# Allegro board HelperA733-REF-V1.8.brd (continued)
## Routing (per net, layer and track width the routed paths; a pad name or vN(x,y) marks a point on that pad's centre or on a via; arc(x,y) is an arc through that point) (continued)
GND_485: length 32.8
  TOP w0.254: C60.2 116.63,18.03 116.63,18.05
  TOP w0.381: R75.1 114.39,14.01 v1(113.81,14.01) 113.24,14.01 R76.1 ; D54.1 106.96,15.44 107.79,16.26 110.01,16.26 110.01,15.63
  TOP w0.508: C59.2 115.31,18.41 115.31,23.55 114.74,24.13 R72.2 ; C59.2 114.78,17.88 110.72,17.88 110.01,17.16 110.01,16.26 ; C59.2 115.31,18.45 116.18,18.45 C60.2
  BOTTOM w0.381: v1(113.81,14.01) 110.39,14.01 110.39,14.01 v1(106.97,14.01)
VBUS1: length 52.5
  TOP w0.152: D64.2 25.83,87 25.92,86.91 26.01,87 CU2.2 ; 25.92,85.57 25.94,85.6 CU3.2 ; 25.89,84.48 26.51,84.48 26.61,84.38 U13.1
  TOP w1.524: J22.4 9.64,87 10.58,87.94 10.58,98.6 12.07,100.09 23.99,100.09 25.11,98.97 J20.5 J20.1 25.11,89.19 25.92,88.38 25.92,85.57 25.89,85.54 25.89,84.48
  BOTTOM w1.524: J23.4 J22.4
VBUS-EN: length 84.1
  TOP w0.152: U1.172 60.11,33.7 62.71,36.3 v1(62.71,66.7) ; v1(32.03,82.16) 31.92,82.01 30.81,80.9 RU1.2 29.54,82.03 U13.4
  BOTTOM w0.152: v1(32.03,82.16) 40.03,82.16 40.49,81.7 40.49,68.88 42.37,67 62.41,67 v1(62.71,66.7)
VBUS-USB: length 21.6
  TOP w0.3: J19.B4 81.91,99.6 82.41,100.1 86.21,100.1 86.71,99.6 J19.A4
  TOP w0.305: 80.51,89.68 79.69,89.68
  TOP w0.635: J19.B4 81.91,97.16 D63.1 ; 78.24,91 78.41,90.83 ; 78.41,90.83 78.82,90.42 C66.1 ; 78.41,90.83 78.41,95.45 79.07,96.11
  TOP w0.762: 79.69,89.68 78.82,89.68 C66.1 ; C63.2 79.07,96.11 79.32,96.36 D63.1
VCC-1V8: length 243.7
  TOP w0.152: v1(48.81,62.2) 48.81,63.1 48.76,63.15 Q9.1 ; C20.2 76.01,96.73 76.12,96.84 U5.2 ; v1(103.51,13.83) 104.11,13.23 104.11,11.86 105.66,10.31 105.66,8.31 109.63,4.34 115.94,4.34 123.11,11.51 135.69,11.51 R54.1 ; 44.01,58.88 43.51,59.38 43.51,59.9 42.51,60.9 v1(42.51,62.2) 42.46,62.25 Q11.1 ; v1(64.91,17) 64.91,26.25 72.31,33.65 v1(72.31,62.7) 72.31,71.27 v1(72.3,71.27) ; 46.51,58.88 45.91,59.48 45.91,61.9 v1(45.61,62.2) 45.61,63.24 Q10.1 ; 41.51,58.88 40.01,60.38 v1(40.01,62.2) ; v1(68.11,11.7) R50.1 ; R48.1 R49.1 69.41,11.5 69.51,11.6 v1(69.51,11.7) ; 73.69,90.8 75.01,90.8 75.21,90.6 75.21,89.7 76.51,88.4 76.51,84.8 v1(78.51,82.8)
  TOP w0.5: 76.12,97.9 U5.2 ; RA20.1 73.69,90.97 76.66,93.95 76.66,95.87 76.51,96.03 C20.2
  BOTTOM w0.152: v1(40.01,62.2) v1(42.51,62.2) v1(45.61,62.2) v1(48.81,62.2) 51.21,62.2 51.71,62.7 72.21,62.7 72.26,62.65 v1(72.31,62.7) ; v1(103.51,13.83) 102.2,13.83 101.37,14.67 97.93,14.67 94.93,17.66 65.57,17.66 v1(64.91,17) 64.91,14.9 v1(68.11,11.7) v1(69.51,11.7) ; v1(72.3,71.27) 72.31,74 72.31,79.5 72.91,80.1 76,80.1 76.45,79.66 77.95,79.66 78.19,79.42 78.63,79.42 78.93,79.71 78.93,82.38 v1(78.51,82.8)
VCC-3V3: length 506.2
  TOP w0.152: v1(110.76,23.26) 110.27,23.26 109.11,22.1 R69.2 ; 144.31,71.9 v1(144.51,72.2) ; D56.2 43.79,19.82 44.11,19.5 45.71,19.5 46.14,19.08 R80.1 R79.1 R77.1 R78.1 ; v1(137.41,57.1) R27.1 ; v1(140.01,72) 139.61,72 139.51,71.9 R17.1 R31.1 ; Q3.1 130.31,23.65 v1(130.31,22.7) 131.64,22.7 R87.2 ; R25.2 136.95,43.45 v1(136.26,43.45) ; 38.51,16.9 38.41,16.9 38.54,17.03 ; 38.51,16.9 38.51,16.64 R119.1 ; 38.51,16.9 38.53,16.9 ; 127.01,19.9 126.96,19.85 v1(126.91,19.9) ; J4.3 141.71,71.9 140.51,73.1 v1(140.41,73.1) ; v1(107.41,84.4) 107.41,85.1 108.56,86.25 R51.1 ; R28.1 v1(138.21,53)
  TOP w0.254: C84.1 23.98,80.46 23.25,80.46 23.16,80.38 ; v1(63.51,81.5) 63.36,81.5 61.35,83.51 61.35,91.04 61.99,91.68 RA16.1 ; U42.9 18.47,80.34 18.94,79.87 21.43,79.87 21.44,79.86 21.9,79.86 21.91,79.87 22.65,79.87 23.16,80.38 ; 23.16,80.38 23.14,80.38 C87.1 ; R52.1 99.51,87.5 99.51,86.91 v1(99.57,86.91) ; v1(67.33,80.98) 67.81,81.46 RA24.1 ; R24.2 v1(136.31,44.93) ; v1(76.52,80.76) 75.7,81.58 RA22.2 ; v1(71.23,80.98) 71.23,81.58 RA23.2 71.21,81.58 ; 108.64,87.5 R51.1 ; R23.2 136.58,42.03 136.46,41.91 v1(136.46,41.44)
  TOP w0.3: v1(77.91,96.4) 77.71,96.4 77.71,93.32 76.45,92.07 76.45,89.11 76.91,88.65 76.91,85.2 78.73,83.38 78.75,83.38 79.09,83.04 79.09,81.4 v1(78.33,80.63) ; v1(61.74,81.63) 61.59,81.48 55.34,81.48 51.83,85 44.44,85 43.03,83.59 39.06,83.59 38.37,82.9 33.81,82.9 30.91,80 25.7,80 C84.1 ; v1(63.51,81.5) 63.51,81.31 64.43,80.39 66.74,80.39 v1(67.33,80.98) ; R24.2 136.95,45.4 137.15,45.6 139.71,45.6 140.01,45.3 J5.2 ; J4.2 144.01,72.4 144.31,72.1 144.31,71.9 J4.3
  TOP w0.305: v1(114.63,23.27) 114.63,19.26 113.91,18.55 110.41,18.55 109.38,17.51 Q1.2 ; 148.21,45.3 J5.2 ; 142.71,72.4 J4.2
  TOP w0.5: J15.1 34.43,10.91 37.22,13.71 38.72,13.71 39.3,14.29 39.3,15.66 38.53,16.43 R119.1 ; FB2.1 107.41,82.05 v1(107.41,84.4) ; v1(101.61,96.3) 101.66,96.25 J7.4
  TOP w0.508: v1(110.76,23.26) 110.76,23.28 C61.1
  TOP w0.6: D56.2 43.49,20.9 J17.1
  TOP w0.762: C45.2 102.94,88.38 D36.2 101.66,88.38 J7.4
  TOP w1: R119.1 38.53,19.18 38.41,19.3 J17.1 ; v1(148.21,49.5) v1(148.21,48.7) 148.21,22.29 144.42,18.5 139.95,18.5 134.35,12.9 127.59,12.9 126.91,13.58 v1(126.91,19.9) ; 127.01,19.9 v1(127.61,19.9) D70.1
  BOTTOM w0.152: v1(140.01,72) 140.01,72.6 140.46,73.05 v1(140.41,73.1) ; v1(130.31,22.7) 130.31,20.2 130.01,19.9 v1(127.61,19.9)
  BOTTOM w0.254: v1(101.61,89.2) 99.87,89.2 99.57,88.9 v1(99.57,86.91) ; 78.33,80.61 v1(78.33,80.63) ; v1(136.46,41.44) 136.31,41.59 v1(136.31,44.93) 136.31,46.8 138.21,48.7 v1(138.21,53) 138.21,56.6 137.71,57.1 v1(137.41,57.1)
  BOTTOM w0.3: 76.5,80.74 76.45,80.8 71.41,80.8 v1(71.23,80.98) 70.91,81.3 67.65,81.3 v1(67.33,80.98) ; 76.5,80.74 v1(76.52,80.76) ; 76.5,80.74 76.91,80.34 78.01,80.34 78.31,80.64 v1(78.33,80.63) ; v1(61.74,81.63) 61.74,81.6 63.41,81.6 v1(63.51,81.5)
  BOTTOM w0.5: J16.3 60.61,7.74 59.8,8.55 42.26,8.55 39.9,10.91 J14.1 J15.1 ; v1(101.61,96.3) 101.51,96.4 89.81,96.4 88.21,98 78.91,98 77.91,97 v1(77.91,96.4)
  BOTTOM w0.508: v1(114.63,23.27) 116.15,23.27 116.15,23.27 116.1,23.18
  BOTTOM w1: v1(114.63,23.27) 114.63,23.26 ; 114.63,23.26 v1(110.76,23.26) 105.2,23.26 105.17,23.3 89.81,23.3 87.01,20.5 57.01,20.5 56.31,21.2 51.64,21.2 51.01,20.58 38.74,20.58 J17.1 ; 114.63,23.26 120.35,23.26 123.71,19.9 v1(126.91,19.9) v1(127.61,19.9) ; v1(101.61,89.2) 106.41,84.4 v1(107.41,84.4) 132.31,84.4 v1(144.51,72.2) 146.61,70.1 146.61,52.9 148.21,51.3 v1(148.21,49.5) v1(148.21,48.7)
VCC_4G: length 73.5
  TOP w0.152: R117.1 C92.1 ; CON3.2 28.74,66.28 28.81,66.2 ; C99.1 C101.1 28.29,53.69 C94.1 25.5,51.71 25.39,51.6 L7.2 ; D73.1 7.71,79 9.11,77.6 CON3.41
  TOP w0.3: R100.2 17.99,62.92 15.91,64.99 CON3.24
  TOP w0.6: 15.91,67.86 CON3.24 ; 4.71,68.4 CON3.52
  TOP w0.635: 4.71,68.4 4.71,69 4.91,69.2 ; CON3.39 9.91,73.7 9.28,73.7 9.11,73.87 CON3.41
  TOP w1: 15.91,69.2 15.91,67.86
  TOP w1.524: 4.71,68.4 5.51,69.2 9.41,69.2 ; C100.1 28.29,59.98 28.81,60.5 28.81,67.9 27.51,69.2 9.41,69.2 ; 9.41,69.2 9.41,73.56 9.28,73.7
VPP/VCC: length 5
  TOP w0.203: UA1.15 65.6,87.08 65.52,87.08
  TOP w0.254: 65.52,87.08 65.51,87.08 64.9,87.69 64.22,87.69 63.84,87.3 63.73,87.26 63.73,85.39 63.84,85.4
VRN/AGND: length 2.9
  TOP w0.203: UA1.6 68.69,90.17
  TOP w0.254: RA26.1 67.41,91.56 67.58,91.56 68.68,90.46 68.68,90.18 68.69,90.17 68.69,90.17
VRP/AVCC: length 2.7
  TOP w0.203: UA1.5 69.09,90.25
  TOP w0.254: 69.09,90.25 69.09,90.63 68.44,91.27 68.44,91.52 CA1.2
4G-EN: length 71.4
  TOP w0.152: U1.173 59.71,32.7 63.11,36.1 63.11,46 v1(63.31,46.2) ; R118.1 v1(19.71,57.6) 20.77,57.6 20.82,57.55 U43.4
  BOTTOM w0.152: v1(19.71,57.6) 19.71,50.02 20.14,49.6 38.61,49.6 42.81,45.4 60.91,45.4 61.71,46.2 v1(63.31,46.2)
340_3V3: length 16.3
  TOP w0.203: U11.9 85.14,89.15
  TOP w0.381: U12.7 83.31,86 82.91,86.4 82.91,87.2 83.21,87.5 U12.10 84.99,87.5
  TOP w0.508: C68.1 87.29,89.81 87.29,89.1 ; 87.29,87.5 87.29,85.19 C71.1 86.6,84.44 86.54,84.44 ; 87.29,87.5 87.29,89.1 ; 87.29,87.5 84.99,87.5 ; 87.29,89.1 87.24,89.15 85.14,89.15
485_1+: length 14
  TOP w0.381: R73.2 R70.2 ; R73.2 110.41,14 110.31,14.06 111.28,15.02 U9.6 ; R73.2 110.39,13.23 D53.1 110.35,12.3 110.94,11.72 110.94,10.67 D54.2 110.92,9.74 110.92,6.95 J13.2
485_1-: length 13.4
  TOP w0.381: R76.2 112.39,12.88 D53.2 112.01,12.3 111.47,11.76 111.47,10.69 D52.1 111.41,9.65 111.41,6.5 J13.1 ; R76.2 R73.1 ; R76.2 112.39,15.63 U9.7
AECRN: length 1.5
  TOP w0.152: 65.34,95.1 65.34,95.3 66.39,95.3 RA25.1
AECRP: length 1.4
  TOP w0.152: RA21.1 66.39,95.9 65.34,95.9 65.34,96.1
AFVCC-CSI: length 14.4
  TOP w0.305: 89.52,7.23 89.36,7.08 CON1.36
  TOP w0.381: 90.29,8.01 89.52,7.23
  TOP w0.508: 90.29,8.01 93.17,8.01 93.81,8.64 93.81,10.47 93.62,10.66 D9.2 CP1.1 93.64,12.08 93.81,12.25 93.81,14.4 94.01,14.6 94.01,14.97 U1.34
AGND/VRP: length 3.3
  TOP w0.203: UA1.7 68.29,90.27 68.22,90.34
  TOP w0.254: 68.22,90.34 67.44,91.13 66.96,91.13 RA4.1
AP-RESET: length 114.5
  TOP w0.152: v1(53.81,18.3) 53.51,18.6 53.51,19 55.51,21 55.51,23.6 56.01,24.1 56.01,35.9 58.81,38.7 U1.167 ; K3.2 130.31,9.24 D40.2 130.57,10.13 130.1,10.6 123.38,10.6 116.18,3.4 108.97,3.4 104.71,7.66 104.71,9.84 102.46,12.09 102.46,14.31 v1(102.14,14.63)
  BOTTOM w0.152: v1(53.81,18.3) 55.06,18.3 55.22,18.14 94.82,18.14 97.98,14.98 101.79,14.98 v1(102.14,14.63)
AVCC/VRA1: length 4.8
  TOP w0.203: UA1.8 67.89,90.07 67.78,90.18
  TOP w0.254: 67.78,90.18 67.24,90.72 66.79,90.72 66.42,91.1 65.92,91.1 65.41,91.6 65.41,91.63 64.46,91.63 RA15.2
BL-PWMI: length 4.3
  TOP w0.152: CL1.1 R26.1 11.54,43.99 11.54,44 11.58,43.96 ; CL1.1 RL1.2 ; CL1.1 RL2.2
CLKOUT-125M: length 2.5
  TOP w0.203: RE12.2 119.59,75.1 U10.35
CLKREQN: length 10.7
  TOP w0.152: J12.52 48.01,66.4 47.51,65.9 45.31,65.9 44.61,65.2 Q10.3 44.61,60.33 R230.2
CODEC-AVCC: length 43.9
  TOP w0.152: 73.63,82.2 RA13.1
  TOP w0.203: UA1.25 68.69,83.36 ; 71.99,85.88 UA1.33
  TOP w0.254: RA15.1 RA16.2 62.37,92.53 v1(62.37,92.51) 62.21,92.53 61.81,92.53 60.94,91.65 60.94,83.24 64.17,80.01 68.11,80.01 68.69,80.59 68.69,82.76 v1(68.5,82.96) 68.5,82.96 68.69,83.15 68.69,83.36 ; 73.79,84.2 CA16.2 ; CA16.2 73.64,84.2 ; CA16.2 RA17.2 73.29,82.8 v1(73.29,82.7) 73.29,82.54 73.63,82.2 ; 73.64,84.2 73.67,84.17 ; 73.64,84.2 73.01,84.2 72.85,84.37 72.85,85.3 72.27,85.88 71.99,85.88 ; RA8.2 62.01,86.3 61.76,86.55 61.76,90.46 v1(62.38,91.08)
  BOTTOM w0.254: v1(73.29,82.7) 68.75,82.7 v1(68.5,82.96) ; v1(62.38,91.08) 62.38,92.51 v1(62.37,92.51)
CODEC-CPVDD: length 31.8
  TOP w0.254: RA7.1 62.25,85.4 61.88,85.02 61.88,83.56 63.34,82.1 63.71,82.1 64.24,81.58 64.67,81.58 ; 64.67,81.58 RA14.1 ; 64.67,81.58 v1(64.67,80.98) ; 74.54,89.29 74.56,89.25 RA18.1 75.12,89.2 76.11,88.21 76.11,84.62 77.91,82.82 77.91,82.48 78.32,82.07 v1(78.32,81.76)
  TOP w0.3: RA20.2 RA18.1
  BOTTOM w0.254: v1(78.32,81.76) 76.32,81.76 76.16,81.6 72.85,81.6 72.45,82 65.53,82 64.97,81.44 64.97,81.28 v1(64.67,80.98)
CODEC-IRQ: length 23.1
  TOP w0.152: v1(78.42,79.92) 78.63,79.71 81.24,79.71 83.38,77.57 83.38,76.33 U1.108 ; UA1.24 68.29,83.47 67.81,82.99 RA24.2 68.33,81.9 68.33,81.03 v1(68.01,80.71)
  BOTTOM w0.152: v1(68.01,80.71) 68.22,80.92 70.57,80.92 71.08,80.41 76.15,80.41 76.63,79.92 v1(78.42,79.92)
CODEC-RST: length 11.8
  TOP w0.152: U1.109 83.01,77.51 81.11,79.41 78.21,79.41 77.79,79.83 77.79,82.05 RA19.2
CPVDD: length 4.3
  TOP w0.203: UA1.22 67.49,83.82 67.35,83.68
  TOP w0.254: RA14.2 CA13.1 65.71,83.22 66.1,83.62 67.28,83.62 67.35,83.68 67.35,83.68
CTP0-INT: length 109.6
  TOP w0.152: U1.180 59.21,25.7 59.31,25.76 59.34,25.7 59.61,25.7 65.81,31.9 v1(65.81,33.9) ; J5.4 142.61,44.23 142.06,44.23 v1(141.61,44.2) ; v1(141.66,42.05) 141.66,42.03 D20.6 D20.5 R23.1 137.33,42.51 136.17,42.51 135.65,41.99 135.65,39.05 132.15,35.55 128.19,35.55 127.26,36.49 127.26,39.45 128.01,40.2 129.71,40.2 J3.3
  BOTTOM w0.152: J3.3 129.71,40.2 125.87,40.2 122.47,36.8 97.11,36.8 93.91,33.6 67.01,33.6 66.71,33.9 v1(65.81,33.9) ; v1(141.61,44.2) 141.61,43.15 141.66,43.1 v1(141.66,42.05)
CTP0-RST: length 104.2
  TOP w0.152: v1(140.91,46.1) 140.81,46.1 141.11,45.8 J5.1 ; v1(140.91,42.55) 140.99,42.54 140.99,42.53 D20.7 D20.4 138.15,42.53 137.88,42.8 135.86,42.8 135.4,42.34 135.4,39.16 132.09,35.85 128.25,35.85 127.51,36.59 127.51,38.55 128.16,39.2 J3.4 ; U1.181 59.21,24.7 66.51,32 v1(66.51,33.2)
  BOTTOM w0.152: J3.4 125.44,39.2 122.74,36.49 98.41,36.49 98.4,36.5 97.21,36.5 94.01,33.3 66.71,33.3 66.61,33.2 v1(66.51,33.2) ; v1(140.91,42.55) 140.92,42.56 140.92,45.79 v1(140.91,46.1)
DC_EN: length 1.6
  TOP w0.152: U2.4 13.72,22.09 13.71,22.1 R5.2
DCIN: length 59.3
  TOP w0.152: 18.4,43.23 C10.1 ; R240.2 23.01,17.4 22.91,17.3 20.14,17.3 19.91,17.53 19.91,18.7 C3.1 ; 11.41,21.38 12.07,22.1 R5.1 ; C9.1 18.41,45.26 17.99,45.68 17.99,47.4
  TOP w0.254: 5.33,44.65 5.33,44.03 5.71,43.65 CON2.26 ; 5.33,44.65 5.07,44.39 ; 5.33,44.65 5.51,44.65 ; 5.51,44.65 6.01,45.15 CON2.29 ; 5.51,44.65 CON2.28 ; 5.51,44.65 5.51,44.4 ; CON2.27 5.71,44.15 5.47,44.39
  TOP w0.3: 17.99,47.4 R233.1
  TOP w1.524: 5.51,44.4 5.51,44.39 5.07,44.39 2.65,41.97 2.65,27.32 3.7,26.26 6.53,26.26 12.69,20.1 C2.1
DM1: length 21.3
  TOP w0.254: U42.3 13.7,83 13.57,82.87 10.65,82.87 9.71,81.93 4.01,81.93 3.34,82.6 3.34,83.59 D78.1 1.52,86.03 1.52,89.42 1.85,89.74 2.27,89.74 J23.3
DM2: length 17.2
  TOP w0.254: U42.1 13.47,84.06 13.37,83.95 10.73,83.95 9.42,82.64 7.43,82.64 7.19,82.88 7.19,83.64 D76.1 7.19,84.17 7.19,86.06 6.22,87.03 6.22,89.61 6.46,89.84 7.17,89.84 J22.3
DM3: length 10.1
  TOP w0.254: U42.15 18.31,83.53 18.54,83.61 21.56,86.63 21.56,86.66 21.9,87 D65.1 21.71,87.24 21.71,90.06 22.61,90.96 J20.2
DM4: length 23.4
  TOP w0.254: U42.13 17.51,82.47 17.28,82.55 16.64,82.55 15.85,83.35 15.85,84.65 16.63,85.43 17.1,85.43 17.33,85.67 17.33,86.64 D67.1 17.02,87 17.41,87.39 17.41,88.2 16.4,89.21 16.4,94.91 17.27,95.79 21.03,95.79 21.67,95.15 21.67,94.64 22.61,93.7
DP1: length 22.6
  TOP w0.254: J23.2 2.11,90.1 1.7,90.1 1.17,89.56 1.17,85.87 2.94,84.1 2.94,83.9 D79.1 2.67,83.82 2.64,83.82 2.98,83.48 2.98,82.45 3.86,81.57 9.86,81.57 10.8,82.51 13.58,82.51 13.63,82.47 U42.4
DP2: length 18.3
  TOP w0.254: J22.2 7.21,90.2 6.31,90.2 5.86,89.75 5.86,86.89 6.83,85.92 6.83,84.17 D77.1 6.57,83.85 6.83,83.58 6.83,82.73 7.28,82.29 9.56,82.29 10.88,83.6 13.41,83.6 13.48,83.53 U42.2
DP3: length 8.8
  TOP w0.254: J20.3 21.36,90.05 21.36,87.39 D66.1 20.97,86.95 20.96,86.95 20.96,86.54 18.48,84.06 U42.16
DP4: length 21.4
  TOP w0.254: J20.7 21.31,94.42 21.31,95 20.88,95.43 17.42,95.43 16.76,94.77 16.76,89.35 17.78,88.33 17.78,87.23 18,87 D68.1 17.69,86.64 17.69,85.52 17.24,85.07 16.78,85.07 16.2,84.5 16.2,83.49 16.79,82.91 17.37,82.91 17.45,83 U42.14
EDP-AUXN: length 63.5
  TOP w0.152: U1.135 58.54,70.23 57.71,70.23 55.88,68.4 55.88,62.35 29.51,35.98 13.99,35.98 C28.1
EDP-AUXP: length 63.4
  TOP w0.152: C25.1 13.99,35.73 29.62,35.73 56.14,62.25 56.14,68.29 57.82,69.97 58.54,69.97 58.81,69.7 U1.136
EDP-EN: length 96.5
  TOP w0.152: v1(51.58,60.51) 51.58,60.13 29.94,38.49 17.42,38.49 14.41,41.5 13.29,41.5 13.12,41.34 13.12,41.32 12.8,41 D17.2 12.56,41 12.56,41.32 11.88,42 R22.1 ; v1(63.31,61.7) 63.31,61.6 63.21,61.5 63.21,47.11 63.82,46.5 63.82,45.81 63.51,45.5 63.51,35.5 59.71,31.7 U1.174
  BOTTOM w0.152: v1(51.58,60.51) 52.87,61.8 63.31,61.8 v1(63.31,61.7)
EDP-HPD: length 66.5
  TOP w0.152: D15.2 11.57,40.56 11.54,40.53 R21.1 R20.2 13.21,39.68 13.21,39.43 R19.1 13.64,38.58 14.21,38 30.06,38 54.67,62.61 54.67,66.25 55.48,67.06 55.48,68.37 58.81,71.7 U1.134
EDP-PWM: length 96.1
  TOP w0.152: v1(64.11,61.8) 64.11,61.3 63.61,60.8 63.61,47.4 64.21,46.8 64.21,45.7 63.81,45.3 63.81,35 59.71,30.9 59.71,30.82 59.59,30.7 U1.175 ; RL1.1 14.38,42 17.48,38.9 29.78,38.9 50.81,59.93 50.81,60.33 v1(50.82,60.33)
  BOTTOM w0.152: v1(50.82,60.33) 50.82,60.56 52.56,62.3 63.61,62.3 v1(64.11,61.8)
EDP-TX0N: length 63.4
  TOP w0.152: U1.138 58.81,67.7 58.44,68.07 57.16,68.07 56.84,67.75 56.84,61.85 28.72,33.73 14.07,33.73 13.66,33.32 13.62,33.32 C23.1
EDP-TX0P: length 63.4
  TOP w0.152: C24.1 13.62,34.4 13.66,34.4 14.07,33.98 28.61,33.98 56.58,61.95 56.58,67.85 57.06,68.33 58.44,68.33 58.81,68.7 U1.137
EDP-TX1N: length 62.5
  TOP w0.152: U1.140 58.81,65.7 58.44,66.07 57.76,66.07 57.54,65.85 57.54,61.55 27.72,31.73 14.07,31.73 13.66,31.32 13.62,31.32 C21.1
EDP-TX1P: length 62.5
  TOP w0.152: C22.1 13.62,32.4 13.66,32.4 14.07,31.98 27.61,31.98 57.28,61.65 57.28,65.95 57.66,66.33 58.44,66.33 58.81,66.7 U1.139
FEL: length 121.9
  TOP w0.152: v1(62.11,38.8) 62.11,60.3 61.71,60.7 U1.145 ; v1(94.91,38.8) 95.08,38.63 95.08,20.21 95.78,19.5 97.22,19.5 98.25,18.47 98.25,17.45 102.03,13.66 102.03,11.98 104.39,9.63 104.39,7.62 108.86,3.15 116.31,3.15 123.17,10.01 124.86,10.01 125.04,9.83 125.26,9.5 D39.1 125.37,7.36 K1.1
  BOTTOM w0.152: v1(62.11,38.8) 62.21,38.9 94.91,38.9 95.01,38.8 v1(94.91,38.8)
GPADC4: length 57.4
  TOP w0.152: U1.155 52.35,50.7 48.41,46.76 48.41,17 50.41,15 D59.2 D59.9 50.41,7.4 49.61,6.6 49.61,4.2 J16.14
GPADC5: length 54
  TOP w0.152: J16.13 50.61,6.56 50.91,6.86 D59.10 D59.1 50.91,15.1 48.71,17.3 48.71,46.54 51.87,49.7 U1.156
GPADC6: length 57.2
  TOP w0.152: J16.12 51.61,4.2 51.61,7 52.91,8.3 D58.6 D58.5 52.91,13.6 49.02,17.49 49.02,46.34 51.99,49.32 58.19,49.32 58.81,48.7 U1.157
HBIAS: length 43.4
  TOP w0.152: UA1.2 70.29,89.9 70.51,90.12 70.51,91.41 v1(70.34,91.41) ; C54.2 38.81,88.83 ; 38.81,88.83 38.81,88.4 40.41,86.8 42.69,86.8 43.48,86.02 43.48,85.77 v1(43.37,85.77) ; 38.81,88.83 38.34,88.83 38.21,88.96 38.21,89.22 R64.2
  BOTTOM w0.152: v1(43.37,85.77) 43.58,85.97 45.17,85.97 45.57,85.57 52.2,85.57 53.86,83.91 64.11,83.91 66.83,86.63 66.83,89.61 68.97,91.75 70,91.75 v1(70.34,91.41)
HCEC: length 38.4
  TOP w0.152: U1.39 99.16,18.7 107.08,26.62 129.72,26.62 130.16,26.17 130.16,25.55 Q3.2 130.82,24.73 130.82,23.61 131.03,23.4 R87.1
HDMI-5V: length 16.7
  TOP w0.152: R90.2 R91.2 133.69,21.53 133.71,21.55 ; 139.67,25.1 U14.18 ; 134.52,22.4 D71.1
  TOP w0.35: 140.21,25.1 139.67,25.1
  TOP w0.5: 140.21,25.1 140.81,25.1 141.11,24.8 141.11,24.1 140.81,23.8 135.11,23.8 134.57,23.26 D71.1 134.61,22.15 134.61,21.8 134.36,21.55 133.36,21.55 133.01,21.9 D69.2
  TOP w0.762: 132.02,21.9 D69.2
HDMI-HCEC: length 13.9
  TOP w0.152: v1(132.11,27.7) 132.61,27.7 132.91,27.4 U16.1 U16.10 134.93,27.4 135.13,27.6 U14.13 ; v1(128.01,25.5) 127.97,25.46 Q3.3 126.69,24.6 R88.2
  BOTTOM w0.152: v1(132.11,27.7) 129.91,25.5 v1(128.01,25.5)
HHPD: length 37.1
  TOP w0.152: U1.40 99.7,19.7 106.93,26.92 129.96,26.92 R89.1 R92.1
HHPD1: length 6.5
  TOP w0.152: U14.19 137.01,24.6 136.61,25 135.81,25 135.41,25.4 U16.6 U16.5 R89.2
HP-DET: length 44.2
  TOP w0.152: v1(75.15,83.71) 75.24,83.8 75.24,85.96 75,86.2 RA11.2 ; R62.1 42.11,88.57 45.21,85.47 51.95,85.47 55.24,82.18 61.19,82.18 61.18,82.2 v1(61.18,82.2) ; RA9.1 75.79,82.2 v1(75.17,82.2) 74.54,82.2 RA13.2
  BOTTOM w0.152: v1(61.18,82.2) 61.18,82.2 61.23,82.14 61.44,82.35 72.91,82.35 73.13,82.13 75.09,82.13 v1(75.17,82.2) 75.17,83.7 v1(75.15,83.71)
HP-DET-PE11: length 22.9
  TOP w0.152: RA9.2 77.23,81.61 v1(77.23,81.07) ; v1(63.04,74.88) 63.04,75.39 U1.129
  BOTTOM w0.152: v1(63.04,74.88) 64.78,74.88 65.3,75.39 65.3,81.33 65.59,81.63 72.02,81.63 72.38,81.27 76.92,81.27 v1(77.23,81.07)
HPOUTFB-1: length 8.1
  TOP w0.152: J11.2 36.91,97.42 36.61,97.12 D47.2 34.44,91.86 RA32.2
HPOUTFB-2: length 40.5
  TOP w0.152: v1(42.49,86.28) 40.33,86.28 38.38,88.23 v1(37.18,88.23) ; R68.2 v1(35.51,88.23) CA27.2 35.09,89.3 34.84,89.3 C57.1 ; C57.1 R65.1 32.6,89.72 32.31,90.01 RN2.1 ; C57.1 RA32.1 ; v1(65.27,85.79) 65.36,85.88 UA1.18
  BOTTOM w0.152: v1(37.18,88.23) 37.18,88.23 v1(35.51,88.23) ; v1(42.49,86.28) 45.3,86.28 45.74,85.84 52.3,85.84 53.92,84.22 63.98,84.22 65.23,85.46 65.23,85.75 v1(65.27,85.79)
HPOUTL-2: length 25.3
  TOP w0.152: UA1.17 65.5,86.28 v1(65.25,86.52) ; C52.2 43.61,88.97 43.78,88.81 43.78,87.91 44.57,87.12 50.44,87.12 v1(50.63,86.93)
  BOTTOM w0.152: v1(65.25,86.52) 64.85,86.13 53.36,86.13 52.36,87.13 50.84,87.13 v1(50.63,86.93)
HPOUTR-2: length 25.8
  TOP w0.152: v1(50.64,87.66) 50.41,87.43 44.7,87.43 44.09,88.04 44.09,88.86 44.2,88.97 C53.2 ; UA1.19 65.67,85.48 65.48,85.29 64.95,85.29 64.54,85.7 v1(64.54,86.63)
  BOTTOM w0.152: v1(50.64,87.66) 50.87,87.44 52.48,87.44 53.49,86.43 64.34,86.43 v1(64.54,86.63)
HS-MIC-1: length 27.5
  TOP w0.152: D46.2 46.01,93.22 v1(46.03,93.22) 46.01,93.6 46.01,101.29 44.41,102.89 J11.5 ; RN2.2 RA31.2 33.31,93.25 v1(33.29,93.27)
  BOTTOM w0.152: v1(33.29,93.27) 33.3,93.27 33.3,93.22 v1(46.03,93.22)
HS-MIC-2: length 7.9
  TOP w0.152: R64.1 C58.1 ; C58.1 36.19,88.88 35.99,89.08 35.99,89.25 CA27.1 v1(35.51,90.37) RN1.1 ; C58.1 R66.2 ; v1(33.78,90.36) 33.78,90.86 33.67,90.97 RA31.1
  BOTTOM w0.152: v1(35.51,90.37) 35.51,90.36 v1(33.78,90.36)
HSCL: length 60.8
  TOP w0.152: U1.42 99.34,21.37 99.91,21.37 106.27,27.73 130.28,27.73 130.91,27.1 132.61,27.1 132.81,26.9 U16.2 U16.9 134.97,26.9 135.17,27.1 136.61,27.1 137.11,26.6 U14.15 141.49,26.6 142.81,25.28 142.81,21.24 141.67,20.1 135.14,20.1 R90.1
HSDA: length 60
  TOP w0.152: R91.1 141.61,20.4 142.51,21.3 142.51,25.22 141.63,26.1 U14.16 137.01,26.1 136.61,26.5 136.06,26.5 135.46,25.9 U16.7 U16.4 132.91,25.9 131.51,25.9 129.99,27.42 106.4,27.42 100.04,21.06 99.37,21.06 U1.41
HTX0N: length 42.1
  TOP w0.152: U14.9 138.51,29.55 137.3,29.55 136.81,30.03 134.93,30.03 134.79,29.9 U15.9 U15.2 133.39,29.9 133.28,30.01 105.19,30.01 100.27,25.08 99.65,25.08 99.26,24.7 U1.45
HTX0P: length 42
  TOP w0.152: U1.46 99.26,25.7 99.62,25.34 100.16,25.34 105.09,30.27 133.27,30.27 133.41,30.4 U15.1 U15.10 134.82,30.4 134.93,30.29 136.94,30.29 137.3,30.65 138.51,30.65 U14.7
HTX1N: length 41.8
  TOP w0.152: U1.47 99.26,26.7 99.65,27.08 100.42,27.08 104.85,31.51 133.28,31.51 133.39,31.4 DE1.5 DE1.6 134.82,31.4 134.93,31.51 136.84,31.51 137.25,31.1 U14.6
HTX1P: length 41.7
  TOP w0.152: U14.4 137.24,32.1 136.91,31.76 134.94,31.76 134.81,31.9 DE1.7 DE1.4 133.4,31.9 133.27,31.77 104.75,31.77 100.32,27.34 99.62,27.34 99.26,27.7 U1.48
HTX2N: length 41.6
  TOP w0.152: U14.3 138.51,32.55 137.3,32.55 136.82,33.03 134.94,33.03 134.82,32.9 DE1.9 DE1.2 133.4,32.9 133.29,33.01 104.57,33.01 100.65,29.08 99.64,29.08 99.26,28.7 U1.49
HTX2P: length 41.6
  TOP w0.152: U1.50 99.26,29.7 99.62,29.34 100.54,29.34 104.47,33.26 133.28,33.26 133.41,33.4 DE1.1 DE1.10 134.82,33.4 134.94,33.28 136.93,33.28 137.3,33.65 138.51,33.65 U14.1
HTXCN: length 42.2
  TOP w0.152: U14.12 137.25,28.1 136.81,28.54 134.95,28.54 134.82,28.4 U15.6 U15.5 133.41,28.4 133.3,28.51 105.67,28.51 100.25,23.08 99.64,23.08 99.26,22.7 U1.43
HTXCP: length 42.1
  TOP w0.152: U14.10 137.24,29.1 136.93,28.79 134.94,28.79 134.83,28.9 U15.7 U15.4 133.41,28.9 133.27,28.76 105.57,28.76 100.14,23.34 99.62,23.34 99.26,23.7 U1.44
HUB1-DM3: length 9.6
  TOP w0.254: U11.15 83.92,92.33 83.83,92.41 83.54,92.41 83.4,92.27 83.4,88.87 81.6,87.07 79.76,87.07 79.69,87 U12.2
HUB1-DP3: length 9.6
  TOP w0.254: U12.1 79.69,87.5 79.76,87.43 81.45,87.43 83.04,89.02 83.04,92.43 83.38,92.77 83.84,92.77 83.93,92.86 84.31,92.86
I2S0-BCLK: length 17.4
  TOP w0.152: UA1.29 70.29,80.45 71.02,79.72 74.28,79.72 75.67,78.33 79.88,78.33 81.01,77.2 U1.111
I2S0-DIN0: length 15.4
  TOP w0.152: UA1.27 69.49,80.38 70.76,79.11 74.03,79.11 75.42,77.72 77.69,77.72 78.01,77.4 U1.114
I2S0-DOUT0: length 16.7
  TOP w0.152: U1.113 79.01,77.16 v1(78.99,77.19) ; UA1.26 69.09,80.34 70.63,78.8 73.9,78.8 75.29,77.41 77.28,77.41 v1(77.48,77.21)
  BOTTOM w0.152: v1(78.99,77.19) 79,77.21 v1(77.48,77.21)
I2S0-LRCK: length 17.1
  TOP w0.152: UA1.28 69.89,80.41 70.89,79.41 74.16,79.41 75.54,78.02 79.63,78.02 80.01,77.64 U1.112
I2S0-MCLK: length 17.9
  TOP w0.152: UA1.30 70.69,80.49 71.16,80.02 74.41,80.02 75.79,78.63 80.31,78.63 82.01,76.93 U1.110
INTB: length 2.9
  TOP w0.152: RE1.2 119.28,72 117.78,73.5 U10.31
IO-RESET: length 91.8
  TOP w0.152: v1(66.01,17.1) U1.6 66.01,15.9 ; K4.1 143.11,15.8 141.82,15.8 141.71,15.69 D42.1 141.22,15.64 141.19,15.68 140.71,15.68 136.26,11.22 123.23,11.22 116.09,4.08 109.01,4.08 105.33,7.76 105.33,10.13 103.49,11.97 v1(103.49,13.04)
  BOTTOM w0.152: v1(103.49,13.04) 103.07,13.46 102.2,13.46 101.26,14.4 97.83,14.4 94.82,17.41 66.32,17.41 v1(66.01,17.1)
IOVDD-CSI: length 22.2
  TOP w0.305: CON1.39 90.26,2.45 90.6,2.12 90.94,2.12
  TOP w0.508: U1.37 98.41,14.3 98.41,12.2 98.28,12.08 CP4.1 D12.2 98.22,10.66 98.62,10.26 98.62,5.84 94.9,2.12 90.94,2.12
LCD0-EN: length 61.6
  TOP w0.152: R41.2 133.11,93.8 133.16,93.75 U6.4 ; R41.2 131.04,94.23 131.07,94.26 D22.1 ; R41.2 130.54,93.3 129.91,93.3 129.75,93.14 129.75,79.5 129.71,79.46 129.71,76.9 v1(130.21,76.4) ; U1.81 100.39,60.7 104.55,64.86 115.78,64.86 117.48,66.56 120.95,66.56 122.46,68.07 125.17,68.07 127.14,70.03 127.14,73.62 J3.40
  BOTTOM w0.152: J3.40 128.91,75.4 129.21,75.4 v1(130.21,76.4)
LCD0-HSYNC: length 36.2
  TOP w0.152: U1.78 99.93,57.7 105.87,63.64 116.3,63.64 117.99,65.33 122.81,65.33 123.39,65.91 124.4,65.91 124.91,65.4 D25.1 126.23,65.4 127.42,64.21 129.72,64.21 J3.29
LCD0-PWM: length 73.1
  TOP w0.152: U1.80 99.82,59.7 100.13,60 100.43,60 104.98,64.55 115.91,64.55 117.61,66.25 121.08,66.25 122.59,67.76 125.3,67.76 127.41,69.87 127.41,73.54 128.07,74.2 129.71,74.2 J3.39 130.07,75.84 130.05,75.84 129.41,76.48 129.41,102.14 130.17,102.9 130.94,102.9 131.1,102.74 131.1,102.72 131.42,102.4 D23.1 131.47,102.26 131.44,102.22 R43.1 131.31,101.4 131.46,101.55 U7.4
LCD0-VSYNC: length 33.6
  TOP w0.152: U1.79 100.5,58.7 105.74,63.94 116.17,63.94 117.86,65.63 122.68,65.63 123.26,66.21 124.45,66.21 124.6,66.36 124.6,66.38 124.92,66.7 D24.1 125.55,66.7 127.05,65.2 J3.30
LCD-PE3: length 17.4
  TOP w0.152: J6.3 66.06,2.93 64.91,4.08 64.91,6.1 65.61,6.8 67.21,6.8 68.71,8.3 68.71,9.34 R50.2 68.62,10.44 68.62,12.42 67.01,14.03 U1.7
LCD-PE4: length 15.5
  TOP w0.152: U1.8 68.01,13.9 68.91,13 68.91,10.44 R49.2 69.41,8.1 67.61,6.3 65.91,6.3 65.51,5.9 65.51,4.75 66.06,4.2 J6.2
LCD-PE5: length 13.7
  TOP w0.152: J6.1 67.68,5.47 70.01,7.8 70.01,9.23 R48.2 71.19,10.41 71.19,11.52 69.01,13.7 U1.9
LCD_LR: length 5.2
  TOP w0.152: J4.33 141.21,56.9 140.11,55.8 139.61,55.8 139.61,55.8 139.36,55.8 R34.1 R27.2
LCD_RST-PL7: length 120.4
  TOP w0.152: v1(100.5,59.43) 105.28,64.2 116.06,64.2 117.76,65.9 121.24,65.9 122.84,67.5 125.4,67.5 127.71,69.81 127.71,71.6 128.3,72.19 132.78,72.19 135.08,74.5 136.91,74.5 137.27,74.14 D28.1 137.27,73.31 137.24,73.28 C33.2 R31.2 138.79,73.3 139.47,73.3 141.87,70.9 J4.5 ; v1(66.71,59.4) 67.11,59 67.11,36.6 59.21,28.7 U1.177
  BOTTOM w0.152: v1(66.71,59.4) 66.71,59.44 100.5,59.44 v1(100.5,59.43)
LCD_UD: length 5.2
  TOP w0.152: R28.2 R35.1 139.36,55.4 140.31,55.4 141.31,56.4 J4.34
LDOIN/RSTN: length 12.1
  TOP w0.152: RA18.2 73.64,89.15 73.64,88.2 CA15.1 ; RA19.1 75.66,83.33 75.66,87.56 75.52,87.7 74.19,87.7 CA15.1 ; RA19.1 75.94,83.2 ; RA19.1 RA17.1 ; CA15.1 73.69,88.07 73.09,87.48 73.09,87.21 72.95,87.08 UA1.36
LED0_AD0: length 46.1
  TOP w0.152: J18.13 115.21,100.38 115.21,99.9 117.51,97.6 117.51,95.4 110.9,88.79 110.9,78.99 111.41,78.48 v1(112.37,78.48) ; U10.32 118.05,73.9 118.84,73.1 v1(118.99,73.1) R84.2
  BOTTOM w0.152: v1(112.37,78.48) 112.37,78.86 113.16,79.66 119.59,79.66 120.08,79.17 120.08,73.26 119.92,73.1 v1(118.99,73.1)
LED1_AD1: length 5.2
  TOP w0.127: U10.33 118.27,74.3 118.71,73.86 119.25,73.86 R83.2 120.19,73.6 120.91,73.6 121.11,73.4 121.11,73.2 121.21,73.1 R82.2
LED+: length 70.7
  TOP w0.152: v1(140.01,95.7) 140.04,96 139.93,95.88
  TOP w0.3: J4.39 144.11,53.9 144.36,53.65 144.11,53.4 J4.40
  TOP w0.5: U7.5 v1(131.81,100.6)
  TOP w0.8: 139.93,95.88 140.01,95.8 v1(140.01,95.7) ; D32.2 139.83,95.88 v1(140.01,95.7) ; v1(140.01,95.7) C42.1 142.39,94.81 142.81,94.39 142.81,91.45 148.91,85.35 148.91,57.2 145.31,53.6 144.41,53.6 144.36,53.65
  BOTTOM w0.8: v1(140.01,95.7) 138.21,95.7 137.01,94.5 133.51,94.5 133.01,95 133.01,99.4 v1(131.81,100.6)
LED-: length 63.5
  TOP w0.152: U7.3 135.71,102.4 134.91,103.2 129.91,103.2 129.11,102.4 129.11,81.5 v1(128.71,81.1) ; v1(139.01,61.9) 139.01,61.1 R44.1
  TOP w0.3: J4.32 141.51,57.4 141.31,57.6 141.21,57.6 141.47,57.86 141.8,57.86 141.84,57.9 J4.31
  TOP w0.6: R44.1 R46.1 R47.1 R45.1 139.71,58.1 140.21,57.6 141.21,57.6
  BOTTOM w0.152: v1(139.01,61.9) 138.51,62.4 138.51,71.38 133.41,76.48 133.41,78.1 130.41,81.1 v1(128.71,81.1)
LRADC0: length 62.1
  TOP w0.152: J9.1 101.11,8.6 101.11,9.59 101.01,9.69 D43.2 101.01,9.85 101.34,10.07 101.49,10.23 101.49,13.78 97.97,17.3 97.97,18.36 97.16,19.17 95.76,19.17 94.65,20.28 94.65,24.16 v1(94.41,24.4) ; U1.183 60.11,22.7 v1(61.31,21.5)
  BOTTOM w0.152: v1(61.31,21.5) 61.41,21.5 61.66,21.25 86.57,21.25 89.46,24.15 94.16,24.15 v1(94.41,24.4)
LVDS0-CKN: length 74.8
  TOP w0.152: v1(125.52,52.15) 125.3,51.94 115.82,51.94 112.91,49.04 112.91,42.58 108.58,38.25 100.99,38.25 100.08,37.34 99.62,37.34 99.26,37.7 U1.58 ; v1(135.56,64.78) 135.82,64.52 137.8,64.52 137.91,64.63 D21.1 D21.10 139.29,64.63 139.4,64.52 140.98,64.52 141.23,64.77 141.9,64.77 142.03,64.9 J4.17
  BOTTOM w0.152: v1(125.52,52.15) 125.76,51.91 125.89,51.91 127.13,53.15 127.13,67.89 127.69,68.45 128.32,68.45 128.71,68.84 J3.34 129.7,70.19 132.16,70.19 134.01,68.35 134.01,65.41 134.9,64.52 135.31,64.52 v1(135.56,64.78)
LVDS0-CKP: length 74.6
  TOP w0.152: U1.57 99.26,36.7 99.62,37.06 100.16,37.06 101.1,38 108.69,38 113.17,42.48 113.17,48.92 115.91,51.66 125.3,51.66 v1(125.52,51.44) ; v1(135.6,63.98) 135.64,63.98 135.63,64.03 135.87,64.27 137.77,64.27 137.91,64.13 D21.2 D21.9 139.3,64.13 139.44,64.27 141.09,64.27 141.33,64.51 141.93,64.51 142.04,64.4 J4.18
  BOTTOM w0.152: v1(125.52,51.44) 125.73,51.66 126,51.66 127.39,53.05 127.39,67.79 127.8,68.2 129.23,68.2 130.23,69.2 J3.33 131.43,69.92 132.07,69.92 133.76,68.24 133.76,65.31 134.8,64.27 135.31,64.27 v1(135.6,63.98)
LVDS0-D0N: length 78.3
  TOP w0.152: v1(139.91,70.23) 139.69,70.44 139.41,70.44 139.3,70.33 D13.9 D13.2 138.18,70.34 136.57,70.34 132.33,66.1 132.33,48.18 132.32,47.84 132.32,46.68 v1(132.66,46.35) ; J4.8 143.89,69.4 143.89,69.41 v1(143.88,69.41) ; U1.52 99.26,31.7 99.62,31.34 100.63,31.34 104.05,34.76 109.5,34.76 115.75,41 115.75,43.35 116.85,44.45 127.96,44.45 J3.10
  BOTTOM w0.152: J3.10 129.7,44.21 131.12,44.21 132.66,45.75 v1(132.66,46.35) ; v1(139.91,70.23) 140.15,70.47 143.51,70.47 144.14,69.84 144.14,69.67 v1(143.88,69.41)
LVDS0-D0P: length 79
  TOP w0.152: J4.9 144.14,68.9 v1(144.64,69.4) ; v1(139.91,70.94) 139.67,70.7 139.43,70.7 139.29,70.83 D13.10 D13.1 137.77,70.83 137.53,70.59 136.47,70.59 132.07,66.2 132.07,48.29 132.07,47.94 132.07,46.43 v1(131.95,46.31) ; J3.9 129.71,44.2 116.95,44.2 116,43.25 116,40.9 109.61,34.5 104.16,34.5 100.74,31.08 99.64,31.08 99.26,30.7 U1.51
  BOTTOM w0.152: v1(139.91,70.94) 140.13,70.72 143.61,70.72 144.39,69.94 144.39,69.64 v1(144.64,69.4) ; J3.9 131.75,45.2 132.2,45.65 132.2,46.06 v1(131.95,46.31)
LVDS0-D1N: length 75.4
  TOP w0.152: J3.12 127.96,46.45 116.53,46.45 114.82,44.75 114.82,41.53 109.22,35.92 103.28,35.92 100.7,33.34 99.62,33.34 99.26,33.7 U1.54 ; v1(143.89,67.91) 143.89,67.9 J4.11 ; v1(133.73,48.89) 133.49,49.13 133.49,66.54 135.92,68.97 137.79,68.97 137.92,68.83 D13.5 D13.6 139.3,68.83 139.43,68.97 139.61,68.97 v1(139.85,68.73)
  BOTTOM w0.152: v1(143.89,67.91) 144.13,68.16 144.13,68.44 143.93,68.64 142.82,68.64 142.5,68.97 140.09,68.97 v1(139.85,68.73) ; v1(133.73,48.89) 133.74,48.89 133.23,49.4 132.54,49.4 131.35,48.2 130.22,48.2 129.22,47.2 J3.12
LVDS0-D1P: length 76.3
  TOP w0.152: v1(139.85,69.44) 139.64,69.22 139.42,69.22 139.31,69.33 D13.7 D13.4 137.91,69.33 137.8,69.22 135.81,69.22 133.24,66.64 133.24,49.1 v1(133.02,48.89) ; J3.11 129.71,46.2 116.63,46.2 115.08,44.65 115.08,41.42 109.32,35.66 103.38,35.66 100.78,33.06 99.62,33.06 99.26,32.7 U1.53 ; J4.12 144.09,67.4 144.64,67.94 v1(144.64,68)
  BOTTOM w0.152: v1(144.64,68) 144.39,68.25 144.39,68.55 144.03,68.9 142.93,68.9 142.61,69.22 140.07,69.22 v1(139.85,69.44) ; v1(133.02,48.89) 132.8,49.11 132.62,49.11 J3.11
LVDS0-D2N: length 73.9
  TOP w0.152: J4.14 143.91,66.4 v1(143.84,66.41) ; 139.08,66.4 139.14,66.4 139.14,66.98 139.11,67 ; v1(134.84,50.24) 134.6,50.48 134.6,65.52 136.08,67 139.11,67 ; 139.11,67 139.71,67 v1(139.81,66.9) ; J3.14 127.96,48.45 116.76,48.45 113.93,45.63 113.93,42.18 108.74,36.98 102.42,36.98 100.78,35.34 99.62,35.34 99.26,35.7 U1.56
  BOTTOM w0.152: J3.14 129.21,49.2 130.2,50.19 131.34,50.19 132.62,51.47 134.21,51.47 134.63,51.05 134.63,50.45 v1(134.84,50.24) ; v1(139.81,66.9) 140.08,67.17 142.15,67.17 142.23,67.09 143.91,67.09 144.1,66.9 144.1,66.68 v1(143.84,66.41)
LVDS0-D2P: length 75.2
  TOP w0.152: v1(134.13,50.24) 134.35,50.45 134.35,65.63 135.98,67.26 139.12,67.26 ; 139.12,67.26 139.12,67.81 ; 139.12,67.26 139.4,67.26 139.81,67.66 v1(139.81,67.7) ; J3.13 129.71,48.2 116.86,48.2 114.19,45.53 114.19,42.05 108.86,36.72 102.52,36.72 100.86,35.06 99.62,35.06 99.26,34.7 U1.55 ; J4.15 144.14,65.9 v1(144.64,66.4)
  BOTTOM w0.152: v1(134.13,50.24) 134.37,50.48 134.37,50.94 134.12,51.19 132.7,51.19 J3.13 ; v1(139.81,67.7) 140.08,67.43 142.25,67.43 142.34,67.34 144.02,67.34 144.36,67.01 144.36,66.68 v1(144.64,66.4)
LVDS0-D3N: length 77.4
  TOP w0.152: v1(123.21,53.6) 123.17,53.6 122.91,53.35 115.02,53.35 111.89,50.22 111.89,43 108.2,39.31 99.65,39.31 99.26,39.7 U1.60 ; J4.20 142.07,63.4 141.94,63.28 140.7,63.28 140.44,63.02 139.43,63.02 139.32,63.13 D21.7 D21.4 137.94,63.13 137.8,63 137.58,63 v1(137.34,63.24)
  BOTTOM w0.152: v1(123.21,53.6) 123.31,53.6 123.25,53.56 123.46,53.35 124.35,53.35 126.22,55.22 126.22,69.09 127.59,70.46 127.97,70.46 J3.36 129.22,71.2 130.21,72.19 133.73,72.19 137.08,68.84 137.08,63.5 v1(137.34,63.24)
LVDS0-D3P: length 77.7
  TOP w0.152: J4.21 142.06,62.9 141.93,63.02 140.81,63.02 140.55,62.77 139.43,62.77 139.29,62.63 D21.6 D21.5 137.89,62.63 137.78,62.74 137.56,62.74 v1(137.34,62.53) ; v1(123.21,52.8) 122.94,53.07 115.1,53.07 112.14,50.11 112.14,42.89 108.31,39.06 99.62,39.06 99.26,38.7 U1.59
  BOTTOM w0.152: v1(123.21,52.8) 123.16,52.85 123.4,53.09 124.46,53.09 126.48,55.11 126.48,68.99 127.7,70.2 129.23,70.2 130,70.97 130.48,70.97 J3.35 131.45,71.94 133.62,71.94 136.83,68.73 136.83,63.04 137.34,62.52 v1(137.34,62.53)
LVDS1-CKN: length 36.9
  TOP w0.152: U1.68 99.26,47.7 99.62,47.34 102.33,47.34 117.66,62.67 123.76,62.67 123.89,62.8 D19.9 D19.2 125.31,62.8 125.44,62.66 125.95,62.66 127.41,61.2 J3.26
LVDS1-CKP: length 39.6
  TOP w0.152: J3.25 129.72,60.21 128.04,60.21 125.84,62.41 125.41,62.41 125.3,62.3 D19.1 D19.10 123.87,62.3 123.76,62.41 117.76,62.41 102.43,47.09 99.65,47.09 99.26,46.7 U1.67
LVDS1-D0N: length 41.4
  TOP w0.152: 125.11,54.75 126.04,54.75 127.69,53.11 128.8,53.11 J3.18 ; 125.11,54.75 125.11,55.3 D83.1 ; 125.11,54.75 114.7,54.75 114.7,54.75 114.62,54.75 110.89,51.02 110.89,43.41 108.81,41.33 99.58,41.33 99.21,41.7 U1.62
LVDS1-D0P: length 43.9
  TOP w0.152: D82.1 125.11,53.9 125.11,54.5 ; 125.11,54.5 114.73,54.5 111.15,50.92 111.15,43.31 108.91,41.07 99.58,41.07 99.21,40.7 U1.61 ; 125.11,54.5 125.91,54.5 128.21,52.21 129.72,52.21 J3.17
LVDS1-D1N: length 39.9
  TOP w0.152: U1.64 99.26,43.7 99.62,43.34 105.27,43.34 109.99,48.06 109.99,51.79 116.19,57.99 123.79,57.99 123.9,58.1 D16.9 D16.2 125.07,58.12 125.32,58.12 125.47,57.96 125.82,57.96 126.42,57.36 126.42,56.44 127.67,55.2 J3.20
LVDS1-D1P: length 42.6
  TOP w0.152: J3.19 129.72,54.21 128.3,54.21 126.17,56.34 126.17,57.26 125.72,57.71 125.5,57.71 125.39,57.6 D16.1 D16.10 123.93,57.6 123.82,57.71 116.3,57.71 110.24,51.65 110.24,47.96 105.37,43.09 99.65,43.09 99.26,42.7 U1.63
LVDS1-D2N: length 37.8
  TOP w0.152: J3.22 128.71,56.92 127.73,56.92 127.42,57.24 127.42,58.28 126.23,59.47 125.47,59.47 125.34,59.6 D16.5 D16.6 123.92,59.6 123.81,59.49 115.92,59.49 101.77,45.34 99.62,45.34 99.26,45.7 U1.66
LVDS1-D2P: length 40.1
  TOP w0.152: J3.21 129.72,56.21 127.97,56.21 127.16,57.02 127.16,58.18 126.13,59.21 125.44,59.21 125.33,59.1 D16.4 D16.7 123.9,59.1 123.79,59.21 116,59.21 101.87,45.08 99.65,45.08 99.26,44.7 U1.65
LVDS1-D3N: length 37.1
  TOP w0.152: U1.70 99.26,49.7 99.62,49.34 102.94,49.34 117.76,64.16 123.78,64.16 123.91,64.3 D19.6 D19.5 125.35,64.3 125.48,64.16 125.87,64.16 127.57,62.46 127.98,62.46 128.12,62.6 128.12,62.61 J3.28
LVDS1-D3P: length 39.2
  TOP w0.152: U1.69 99.26,48.7 99.65,49.09 103.04,49.09 117.87,63.91 123.77,63.91 123.88,63.8 D19.7 D19.4 125.36,63.8 125.47,63.91 125.77,63.91 127.47,62.21 129.72,62.21 J3.27
MBIAS: length 10.5
  TOP w0.25: UA1.38 72.29,87.88 v1(72.51,88.1) ; CA4.2 RA1.2 73.8,95.06 v1(73.8,93.54)
  BOTTOM w0.25: v1(73.8,93.54) 73.91,93.42 73.91,88.37 73.64,88.1 v1(72.51,88.1)
MCSI0-MCLK: length 10.1
  TOP w0.152: CON1.26 86.36,7.79 86.84,8.26 D7.1 D7.10 86.84,13.77 86.01,14.6 U1.26
MCSI2-MCLK: length 9.9
  TOP w0.152: U1.27 87.01,14.23 87.34,13.91 87.34,8.15 86.96,7.77 CON1.28
MCSI-RST-F: length 13.3
  TOP w0.152: v1(88.39,8.71) 88.84,9.15 D7.5 D7.6 88.84,14.08 89.01,14.25 U1.29 ; v1(87.86,4.6) 87.86,4.6 CON1.31
  BOTTOM w0.152: v1(87.86,4.6) 87.86,8.17 v1(88.39,8.71)
MCSI-RST-R: length 11.2
  TOP w0.152: CON1.32 88.16,6.55 88.38,6.76 88.38,6.98 89.79,8.4 89.79,8.92 90.28,9.41 90.29,9.41 90.41,9.52 D8.7 D8.4 90.41,11.39 89.89,11.91 89.89,14.11 91.01,15.22 U1.31
MCSI-SCK-TWI2: length 14.6
  TOP w0.152: v1(91.39,8.71) 91.39,9.39 91.41,9.41 D8.9 D8.2 91.41,11.26 R15.2 91.11,12.6 91.11,14.2 92.01,15.1 U1.32 ; 88.92,5.11 v1(89.09,4.91) 88.96,5.15 88.87,5.12 88.76,5.23 CON1.34
  BOTTOM w0.152: v1(91.39,8.71) 91.65,8.45 91.65,8.32 89.3,5.97 89.3,5.11 v1(89.09,4.91)
MCSI-SDA-TWI2: length 15.1
  TOP w0.152: U1.33 91.41,14.1 91.41,12.56 R16.2 91.89,11.51 91.91,11.49 D8.1 D8.10 91.91,9.19 92.19,8.91 v1(92.19,8.71) ; v1(89.28,4.11) 89.06,3.89 89.06,2.9
  BOTTOM w0.152: v1(89.28,4.11) 89.61,4.43 89.61,5.85 92.19,8.44 v1(92.19,8.71)
MCSI-STBY-F: length 10.1
  TOP w0.152: CON1.30 87.56,7.6 87.73,7.77 87.73,8.88 88.34,9.48 88.34,11.07 88.43,11.17 88.43,13.81 88.01,14.23 U1.28
MCSI-STBY-R: length 13.8
  TOP w0.152: CON1.33 88.46,4.17 v1(88.49,4.21) ; v1(88.52,7.88) 89.29,8.66 89.29,9.12 89.91,9.73 D8.6 D8.5 89.91,11.29 89.49,11.7 89.49,14.51 90.01,15.02 U1.30
  BOTTOM w0.152: v1(88.52,7.88) 88.47,7.83 88.49,7.81 v1(88.49,4.21)
MCSIA-CKN: length 14.8
  TOP w0.152: v1(80.83,9.1) 81.07,9.34 81.07,9.52 80.94,9.66 D5.1 D5.10 80.94,11.06 81.07,11.2 81.07,11.85 78.4,14.53 78.4,15.06 78.01,15.45 U1.18 ; v1(83.25,5) 83.33,5 82.76,5.57 CON1.14
  BOTTOM w0.152: v1(83.25,5) 83.5,5.25 83.5,5.69 81.07,8.12 81.07,8.86 v1(80.83,9.1)
MCSIA-CKP: length 15.7
  TOP w0.152: v1(81.54,9.1) 81.33,9.31 81.33,9.55 81.44,9.66 81.44,11.08 81.33,11.19 81.33,11.96 78.65,14.63 78.65,15.09 79.01,15.45 U1.19 ; CON1.15 83.06,3.82 83.32,4.08 v1(83.23,4.1)
  BOTTOM w0.152: v1(81.54,9.1) 81.33,8.88 81.33,8.23 83.76,5.8 83.76,4.63 v1(83.23,4.1)
MCSIA-D0N: length 16.6
  TOP w0.152: v1(82.51,4.1) 82.49,4.1 82.49,4.1 82.19,4.1 81.86,3.78 CON1.11 ; U1.16 76.01,15.29 76.41,14.89 76.41,14.45 77.23,13.64 77.76,13.64 79.57,11.83 79.57,11.2 79.44,11.07 79.44,9.67 79.57,9.53 79.57,9.36 v1(79.33,9.12)
  BOTTOM w0.152: v1(79.33,9.12) 79.56,8.89 79.56,8.19 82.02,5.73 82.02,4.59 v1(82.51,4.1)
MCSIA-D0P: length 15.1
  TOP w0.152: CON1.12 82.16,5.38 82.53,5.01 v1(82.53,5.01) ; v1(80.04,9.12) 79.83,9.34 79.83,9.53 79.94,9.64 D3.5 D3.6 79.94,11.07 79.82,11.18 79.82,11.93 77.87,13.89 77.33,13.89 76.67,14.55 76.67,14.92 76.99,15.25 76.99,15.68 U1.17
  BOTTOM w0.152: v1(80.04,9.12) 79.82,8.9 79.82,8.29 82.28,5.83 82.28,5.35 82.58,5.05 v1(82.53,5.01)
MCSIA-D1N: length 16.4
  TOP w0.152: CON1.8 80.96,5.15 v1(81.21,4.9) ; v1(77.83,9.13) 78.07,9.37 78.07,9.52 77.94,9.66 D3.1 D3.10 77.94,11.07 78.07,11.2 78.07,11.57 75.94,13.7 75.24,13.7 74.4,14.55 74.4,15.06 74.01,15.45 U1.14
  BOTTOM w0.152: v1(77.83,9.13) 78.07,8.89 78.07,8.02 78.48,7.61 79.17,7.61 81.46,5.31 81.46,5.15 v1(81.21,4.9)
MCSIA-D1P: length 17.2
  TOP w0.152: CON1.9 81.26,4.05 v1(81.21,4.1) ; U1.15 75.01,15.45 74.65,15.09 74.65,14.65 75.35,13.96 76.04,13.96 78.33,11.67 78.33,11.2 78.44,11.09 78.44,9.64 78.33,9.53 78.33,9.35 v1(78.54,9.13)
  BOTTOM w0.152: v1(81.21,4.1) 81.72,4.61 81.72,5.41 79.27,7.86 78.59,7.86 78.33,8.12 78.33,8.92 v1(78.54,9.13)
MCSIA-D2N: length 18.8
  TOP w0.152: U1.12 72.01,15.45 72.4,15.06 72.4,14.07 73.54,12.93 75.46,12.93 76.57,11.81 76.57,11.22 76.44,11.09 76.44,9.65 76.57,9.52 76.57,9.39 v1(76.33,9.15) ; CON1.5 80.06,3.75 80.41,4.1 80.42,4.18 v1(80.42,4.19)
  BOTTOM w0.152: v1(80.42,4.19) 80.42,4.18 80.38,4.13 79.84,4.67 79.84,5.86 78.78,6.92 77.3,6.92 76.55,7.66 76.55,8.92 v1(76.33,9.15)
MCSIA-D2P: length 17.7
  TOP w0.152: v1(80.41,4.9) 80.36,4.95 CON1.6 ; v1(77.04,9.15) 76.83,9.36 76.83,9.53 76.94,9.64 D4.5 D4.6 76.94,11.09 76.83,11.2 76.83,11.92 75.57,13.18 73.64,13.18 72.65,14.17 72.65,15.09 73.01,15.45 U1.13
  BOTTOM w0.152: v1(80.41,4.9) 80.09,5.22 80.09,5.96 78.89,7.17 77.41,7.17 76.81,7.77 76.81,8.91 v1(77.04,9.15)
MCSIA-D3N: length 18.6
  TOP w0.152: U1.10 70.01,15.45 70.39,15.07 70.39,13.96 72.65,11.71 74.78,11.71 75.07,11.42 75.07,11.21 74.94,11.08 D4.10 D4.1 74.94,9.67 75.07,9.53 75.07,9.35 v1(74.83,9.11) ; v1(78.91,4.9) 79.16,5.05 CON1.2
  BOTTOM w0.152: v1(78.91,4.9) 79.21,5.2 79.21,5.55 78.5,6.26 76.81,6.26 75.07,8 75.07,8.87 v1(74.83,9.11)
MCSIA-D3P: length 19.8
  TOP w0.152: v1(75.54,9.11) 75.33,9.33 75.33,9.53 75.44,9.64 75.44,11.07 75.33,11.18 75.33,11.52 74.88,11.97 72.76,11.97 70.65,14.07 70.65,15.09 71.01,15.45 U1.11 ; v1(78.91,4.1) 79.31,4.1 79.46,3.95 CON1.3
  BOTTOM w0.152: v1(78.91,4.1) 79.47,4.66 79.47,5.65 78.61,6.51 76.92,6.51 75.33,8.1 75.33,8.9 v1(75.54,9.11)
MCSIC-CKN: length 14.9
  TOP w0.152: v1(85.27,9.12) 85.51,9.35 85.51,9.54 85.38,9.67 D6.4 D6.7 85.38,11.1 85.51,11.24 85.51,11.87 84.4,12.99 84.4,15.06 84.01,15.45 U1.24 ; v1(86.49,4) 86.06,4 85.46,3.41 CON1.23
  BOTTOM w0.152: v1(86.49,4) 86.44,3.94 86.11,4.27 86.11,6.52 85.51,7.12 85.51,8.88 v1(85.27,9.12)
MCSIC-CKP: length 14.7
  TOP w0.152: v1(85.98,9.12) 85.77,9.33 85.77,9.56 85.88,9.67 D6.5 D6.6 85.88,11.08 85.77,11.19 85.77,11.98 84.65,13.1 84.65,15.09 85.01,15.45 U1.25 ; CON1.24 85.76,4.96 86.02,4.7 v1(86.62,4.7)
  BOTTOM w0.152: 86.74,4.8 v1(86.62,4.7) ; 86.75,4.58 86.36,4.96 86.36,6.63 85.77,7.22 85.77,8.9 v1(85.98,9.12)
MCSIC-D0N: length 14.4
  TOP w0.152: v1(85.29,4.78) 85.29,4.9 84.56,5.63 CON1.20 ; v1(83.77,9.11) 84.01,9.35 84.01,9.58 83.88,9.72 D6.1 D6.10 83.88,11.1 84,11.22 84,11.74 82.39,13.35 82.39,15.07 82.01,15.45 U1.22
  BOTTOM w0.152: v1(83.77,9.11) 84.01,8.87 84.01,7.59 85.54,6.06 85.54,5.04 v1(85.29,4.78)
MCSIC-D0P: length 14.9
  TOP w0.152: U1.23 83.01,15.45 82.65,15.09 82.65,13.46 84.27,11.84 84.27,11.23 84.38,11.12 D6.9 D6.2 84.38,9.69 84.27,9.58 84.27,9.33 v1(84.48,9.11) ; v1(85.32,4.05) 85.01,3.75 85.01,3.5 84.86,3.35 CON1.21
  BOTTOM w0.152: v1(85.32,4.05) 85.8,4.53 85.8,6.17 84.27,7.7 84.27,8.9 v1(84.48,9.11)
MCSIC-D1N: length 15.9
  TOP w0.152: U1.20 80.01,15.45 80.37,15.09 80.37,14.27 82.57,12.07 82.57,11.21 82.44,11.08 82.44,9.66 82.57,9.53 82.57,9.34 v1(82.33,9.1) ; v1(84.61,4.05) 84.56,4.07 83.9,4.07 83.66,3.83 CON1.17
  BOTTOM w0.152: v1(84.61,4.05) 84.56,4.07 84.5,4.1 84.06,4.54 84.06,6.23 82.57,7.72 82.57,8.86 v1(82.33,9.1)
MCSIC-D1P: length 14.5
  TOP w0.152: v1(83.04,9.1) 82.83,9.32 82.83,9.53 82.94,9.64 D5.5 D5.6 82.94,11.08 82.83,11.19 82.83,12.17 80.63,14.37 80.63,15.07 81.01,15.45 U1.21 ; CON1.18 83.96,5.41 84.57,4.8 v1(84.57,4.8)
  BOTTOM w0.152: v1(84.57,4.8) 84.32,5.05 84.32,6.34 82.83,7.83 82.83,8.88 v1(83.04,9.1)
MDI0+: length 16.8
  TOP w0.152: J18.2 123.5,89.11 123.5,88.88 124.31,88.07 124.31,86.2 121.01,82.9 119.44,82.9 118.28,81.74 118.28,80.86 116.44,79.01 116.44,78.28 116.51,78.2 U10.1
MDI0-: length 16.9
  TOP w0.152: U10.2 116.11,78.21 116.18,78.28 116.18,79.12 118.02,80.96 118.02,81.85 119.33,83.15 120.9,83.15 124.06,86.31 124.06,87.97 123.38,88.64 123.17,88.64 122.97,88.44 J18.3
MDI1+: length 16.3
  TOP w0.152: U10.4 115.31,78.2 115.24,78.28 115.24,81.29 119.3,85.35 120.78,85.35 121.91,86.49 121.91,88.11 121.06,88.97 121.06,89.21 J18.4
MDI1-: length 23.3
  TOP w0.152: U10.5 114.91,78.2 114.98,78.28 114.98,81.39 119.2,85.61 120.67,85.61 121.66,86.6 121.66,88.01 120.68,88.99 120.68,90.23 119.64,91.27 118.42,91.27 117.89,90.74 J18.7
MDI2+: length 14.8
  TOP w0.152: U10.6 114.51,78.21 114.44,78.28 114.44,81.75 119.31,86.62 119.31,88.19 119.49,88.37 120.31,88.37 120.56,88.12 120.56,87.88 120.57,87.3 J18.5
MDI2-: length 15.2
  TOP w0.152: J18.6 119.43,89.84 120,89.28 120,88.79 119.84,88.63 119.39,88.63 119.06,88.3 119.06,86.73 114.18,81.86 114.18,78.28 114.11,78.2 U10.7
MDI3+: length 15.5
  TOP w0.152: J18.8 116.35,89.84 115.69,89.18 115.69,88.92 115.84,88.78 116.21,88.78 116.75,88.24 116.75,86.78 112.2,82.23 112.2,79.89 113.25,78.83 113.25,78.3 113.31,78.24 U10.9
MDI3-: length 15.1
  TOP w0.152: U10.10 112.91,78.24 112.99,78.32 112.99,78.73 111.94,79.78 111.94,82.33 116.5,86.89 116.5,88.13 116.1,88.53 115.56,88.53 115.35,88.32 J18.9
MIC2N: length 9.6
  TOP w0.152: DA1.2 70.98,98.96 RA6.1 71.33,99.25 71.33,99.65 70.31,100.67 65.18,100.67 MIC1.2
MIC2N/MIC3N: length 8.2
  TOP w0.152: CA9.1 71.35,94.83 71.35,94.48 72.49,93.35 72.49,88.9 71.92,88.33 71.64,88.28 UA1.39
MIC2P: length 10
  TOP w0.152: DA2.2 72.78,98.93 RA5.1 71.59,99.25 71.59,99.76 70.42,100.93 65.18,100.93 MIC1.1
MIC2P/MIC3P: length 9.7
  TOP w0.152: CA6.1 71.61,94.87 71.61,94.6 72.75,93.46 72.75,88.85 73.02,88.58 73.02,87.89 72.6,87.48 UA1.37
MICIN1N: length 9.2
  TOP w0.152: 67.24,95.1 67.54,95.4 67.9,95.4 68.05,95.25 68.05,94.61 68.53,94.13 69.8,94.13 71.16,92.76 71.16,89.58 71.01,89.43 UA1.1
MICIN1P: length 10.1
  TOP w0.152: 67.24,96.1 67.54,95.8 67.54,95.78 67.66,95.66 68,95.66 68.3,95.36 68.3,94.71 68.63,94.38 69.96,94.38 71.42,92.92 71.42,88.88 71.44,88.85 UA1.40
MICIN4N: length 41.7
  TOP w0.152: v1(42.79,84.17) 42.78,84.16 42.55,84.39 38.04,84.39 37.6,83.95 36.24,83.95 35.92,84.27 35.92,84.71 35.85,84.78 C56.1 ; UA1.4 69.49,89.74 69.55,89.8 69.55,90.42 v1(69.65,90.52)
  BOTTOM w0.152: v1(69.65,90.52) 69.45,90.73 68.95,90.73 67.56,89.33 67.56,86.37 64.36,83.17 53.53,83.17 52.32,84.38 43,84.38 v1(42.79,84.17)
MICIN4P: length 42.8
  TOP w0.152: v1(42.73,84.88) 42.53,84.67 37.92,84.67 37.48,84.23 36.36,84.23 36.2,84.39 36.2,84.7 36.27,84.78 C55.1 ; UA1.3 69.89,89.77 69.83,89.83 69.83,89.98 70.16,90.31 70.16,90.81 69.72,91.25 69.73,91.24 69.69,91.23 v1(69.65,91.24)
  BOTTOM w0.152: v1(42.73,84.88) 42.73,84.88 42.78,84.88 42.98,84.68 52.43,84.68 53.66,83.45 64.25,83.45 67.28,86.49 67.28,89.45 68.84,91.01 69.5,91.01 69.75,91.25 69.64,91.36 69.69,91.3 69.67,91.29 69.71,91.25 69.69,91.23 v1(69.65,91.24)
PA-SHDN-PE15: length 52.8
  TOP w0.152: U1.133 58.81,72.7 57.86,71.75 57.86,71.45 54.89,68.47 54.89,67.9 v1(54.91,67.9) ; v1(48.24,89.25) 48.92,89.93 50.25,89.93 50.44,89.74 R55.2 52.31,89.3 U8.1
  BOTTOM w0.152: v1(54.91,67.9) 42.4,67.9 41.21,69.09 41.21,88.48 41.93,89.2 47.89,89.2 v1(48.24,89.25)
PA-VDD: length 11.6
  TOP w0.635: v1(54.14,97.42) 54.12,97.17 54.85,96.44 U8.6 ; C49.1 50.44,93.14 50.59,93.29 FB1.1 50.59,96.08 50.58,96.08 50.58,97.16 v1(50.59,97.43)
  BOTTOM w0.635: v1(54.14,97.42) 54.14,97.43 v1(50.59,97.43)
PC2: length 60.4
  TOP w0.152: U1.149 57.32,56.7 47.71,47.09 47.71,15.4 46.41,14.1 D60.2 D60.9 46.41,7.2 45.71,6.5 45.71,4.1 J16.18
PC3: length 62.5
  TOP w0.152: U1.147 58.81,58.7 58.31,58.2 57.96,58.2 47.11,47.36 47.11,15.9 44.91,13.7 D60.5 D60.6 44.91,9.2 43.78,8.07 43.78,4.03 J16.20
PC4: length 59.5
  TOP w0.152: U1.148 57.89,57.7 47.41,47.22 47.41,15.7 45.41,13.7 D60.4 D60.7 45.41,9.2 44.11,7.9 44.11,5.8 44.61,5.3 J16.19
PC12: length 56.9
  TOP w0.152: J16.17 46.61,6.3 46.91,6.6 D60.10 D60.1 46.91,14.1 48.01,15.2 48.01,46.91 56.81,55.7 U1.150
PCIE1-REFCLKN: length 27.1
  TOP w0.152: CB11.1 49.03,81.2 49.03,81.45 49.34,81.75 50.72,81.75 54.38,78.1 55.62,78.1 55.77,77.94 55.77,76.69 56.07,76.39 56.59,76.39 56.89,76.69 56.89,77.93 57.04,78.08 57.35,78.08 57.5,77.93 57.5,76.97 57.8,76.67 58.32,76.67 58.62,76.97 58.62,77.93 58.77,78.08 59.07,78.08 59.23,77.93 59.23,76.97 59.53,76.67 60.04,76.67 60.34,76.97 60.34,77.89 60.5,78.04 60.71,78.04 61.49,77.26 61.5,77.26 61.79,76.97 64.25,76.97 64.38,76.83 64.38,76.27 64.01,75.9 U1.128
PCIE1-REFCLKP: length 27.8
  TOP w0.152: U1.127 65.01,75.9 64.64,76.27 64.64,76.94 64.36,77.22 61.89,77.22 60.82,78.3 60.39,78.3 60.09,77.99 60.09,77.07 59.94,76.92 59.63,76.92 59.48,77.07 59.48,78.03 59.18,78.33 58.66,78.33 58.36,78.03 58.36,77.07 58.21,76.92 57.91,76.92 57.75,77.07 57.75,78.03 57.45,78.33 56.94,78.33 56.64,78.03 56.64,76.81 56.48,76.66 56.18,76.66 56.03,76.81 56.03,78.05 55.73,78.35 54.49,78.35 50.83,82.01 49.23,82.01 48.78,81.55 48.78,80.89 CB10.1
PCIE1-RXN: length 34.5
  TOP w0.152: v1(66.15,71.72) 66.38,71.95 66.38,74.33 66.38,75.13 66.01,75.5 U1.126 ; v1(43.41,79.8) 43.67,79.54 43.67,79.19 R243.1
  BOTTOM w0.152: v1(66.15,71.72) 66.38,71.49 66.38,71.26 66.24,71.12 56.78,71.12 49.07,78.83 45.42,78.83 44.96,79.29 44.96,80.54 44.58,80.92 43.98,80.92 43.63,80.56 43.63,80.02 v1(43.41,79.8)
PCIE1-RXP: length 34.5
  TOP w0.152: U1.125 67.01,75.5 66.64,75.13 66.64,74.23 66.64,74.23 66.64,71.95 v1(66.87,71.72) ; R242.1 43.93,79.2 43.93,79.58 v1(44.13,79.77)
  BOTTOM w0.152: v1(66.87,71.72) 66.64,71.49 66.64,71.16 66.34,70.86 56.68,70.86 48.97,78.57 45.32,78.57 44.7,79.19 44.7,80.43 44.47,80.66 44.09,80.66 43.88,80.46 43.88,80.02 v1(44.13,79.77)
PCIE1-TXN: length 35
  TOP w0.152: v1(45.9,79.86) 46.13,79.63 46.13,79.25 CB5.1 ; U1.122 70.01,75.4 70.39,75.02 70.39,74.72 v1(70.15,74.48)
  BOTTOM w0.152: v1(45.9,79.86) 46.12,80.08 46.12,80.46 46.52,80.85 49.11,80.85 56.99,72.98 68.41,72.98 68.71,72.68 68.71,71.61 68.87,71.46 69.17,71.46 69.32,71.61 69.32,72.09 69.62,72.4 70.25,72.4 70.38,72.53 70.38,74.25 v1(70.15,74.48)
PCIE1-TXP: length 35
  TOP w0.152: U1.121 71.01,75.39 70.65,75.03 70.65,74.7 v1(70.87,74.48) ; v1(46.62,79.86) 46.39,79.63 46.39,79.25 CB4.1
  BOTTOM w0.152: v1(46.62,79.86) 46.38,80.09 46.38,80.35 46.63,80.6 49.01,80.6 56.88,72.73 58.23,72.73 68.31,72.73 68.46,72.58 68.46,71.5 68.76,71.2 69.28,71.2 69.58,71.5 69.58,71.99 69.73,72.14 70.35,72.14 70.64,72.43 70.64,74.25 v1(70.87,74.48)
PCIE-3V3: length 131.9
  TOP w0.152: 37.59,65.2 38.21,65.2 ; 36.01,65.4 36.41,65 36.41,63.31 35.51,64.21 ; v1(37.51,65.2) v1(36.81,65.2) 36.11,65.2 ; R19.2 12.29,39.5 11.19,39.5 C26.2 10.69,38.47 10.9,38.26 C27.1 ; CB1.2 51.69,63.03 51.4,63.31 50.21,63.31 ; 37.81,63.31 38.83,63.31 CB6.2
  TOP w0.254: 51.57,78.99 52.14,78.42 52.14,77.23 51.31,76.4 51.31,71.2 52.51,70 J12.70 ; 51.57,78.99 51.25,79.3 51.25,80.36 v1(50.91,80.7) ; 51.57,78.99 51.57,78.93 CB8.2 ; R237.1 50.48,80.72 ; D84.1 36.71,59.39 34.91,59.39 ; CB9.2 46.86,80.8 v1(46.86,81.81) ; R236.1 47.67,80.77
  TOP w0.3: R236.1 46.74,80.72 CB9.2 ; CON2.12 8.31,36.65 8.31,37.15 CON2.13 ; R237.1 50.41,80.7 v1(50.91,80.7)
  TOP w0.305: J12.12 38.01,65.86 37.64,65.49 ; 51.11,65.3 53.01,65.4 J12.72 ; 51.11,65.3 v1(51.41,65.3) v1(52.11,65.3) 52.31,65.3 ; 51.11,65.3 50.81,65.3 50.71,65.2 50.71,65.2 v1(50.71,65.3) ; 37.64,65.49 37.59,65.45 37.59,65.3 ; 37.64,65.49 39.01,65.49 ; J12.70 52.51,66.01 52.31,65.81 52.31,65.3 ; 52.31,65.3 v1(52.81,65.3) 53.51,65.3 J12.74 ; 37.59,65.3 37.59,65.2 v1(37.51,65.2) ; 37.59,65.3 38.05,65.76 38.51,65.76 J12.14 ; 39.01,65.49 39.49,65.49 39.51,65.47 J12.18 ; 39.01,65.49 J12.16 ; J12.4 36.01,65.4 ; 35.51,64.21 J12.2
  TOP w0.8: L2.2 23.91,40.04 23.51,39.64 17.62,39.64 14.71,42.55 v1(14.71,42.6) ; C27.1 10.2,36.9 ; 10.2,36.9 8.31,36.9 ; 10.2,36.9 10.2,36.91 v1(10.21,36.9)
  TOP w1: v1(25.25,19.47) v1(26.16,19.47) 34.95,19.47 36.49,17.92 R119.2
  BOTTOM w0.152: v1(52.81,65.3) v1(52.11,65.3) v1(51.41,65.3) 51.37,65.21
  BOTTOM w0.254: v1(50.91,80.7) 49.8,81.81 v1(46.86,81.81)
  BOTTOM w0.8: v1(14.71,42.6) 10.21,38.1 v1(10.21,36.9)
  BOTTOM w1: v1(25.25,43.53) 25.25,43.53 25.25,20.18 ; 25.96,19.47 25.25,20.18 ; 25.96,19.47 v1(26.16,19.47) ; 25.96,19.47 v1(25.25,19.47) 25.25,20.18
  vias: v1(25.25,42.72)
